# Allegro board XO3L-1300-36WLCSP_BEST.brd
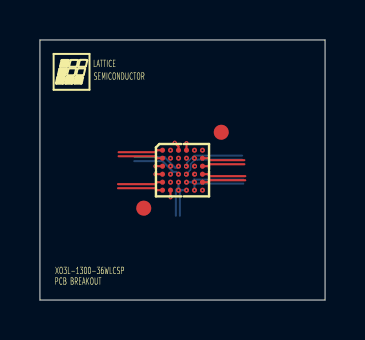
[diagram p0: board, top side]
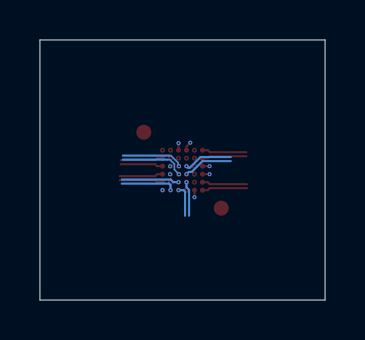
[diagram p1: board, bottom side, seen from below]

Outline 14.28 x 13.02 mm; copper layers: TOP, L2_SIG, L3_PWR, BOTTOM. Coordinates in mm from the lower left corner of the outline.
Outline path: 0,13.02 0,0 14.28,0 14.28,13.02 0,13.02

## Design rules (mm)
net group CDPB6: nets PB6C PB6D
net group CDPB20: nets PB20C PB20D
net group CDPL2: nets PL2C PL2D
net group CDPT10: nets PT10C PT10D
net group CDPT11: nets PT11C PT11D
net group CDPT12: nets PT12C PT12D
net group CDPT15: nets PT15C PT15D
net group CDPT17: nets PT17C PT17D
net group DIFFPAIR0: nets PT10A PT10B
net group DIFFPAIR1: nets PT12A PT12B
net group PB9: nets PB9A PB9B
net group PB11: nets PB11A PB11B
net group PL9: nets PL9A PL9B
net group PT9: nets PT9A PT9B

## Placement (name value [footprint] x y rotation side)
BGA  -  [BGA36N40P6X6_248X254X57B26N]  7.14 6.5 270 top
NOREF  -  []  0.41 10.21 0 top

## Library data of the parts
BGA = BGA36N40P6X6_248X254X57B26N

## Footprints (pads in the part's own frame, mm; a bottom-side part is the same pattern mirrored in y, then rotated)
BGA36N40P6X6_248X254X57B26N
  round 0.75 smd: (-1.9,1.94) (1.9,-1.94)
  round 0.254 smd: A1(-1,-1) A2(-1,-0.6) A3(-1,-0.2) A4(-1,0.2) A5(-1,0.6) A6(-1,1) B1(-0.6,-1) B2(-0.6,-0.6) B3(-0.6,-0.2) B4(-0.6,0.2) B5(-0.6,0.6) B6(-0.6,1) C1(-0.2,-1) C2(-0.2,-0.6) C3(-0.2,-0.2) C4(-0.2,0.2) C5(-0.2,0.6) C6(-0.2,1) D1(0.2,-1) D2(0.2,-0.6) D3(0.2,-0.2) D4(0.2,0.2) D5(0.2,0.6) D6(0.2,1) E1(0.6,-1) E2(0.6,-0.6) E3(0.6,-0.2) E4(0.6,0.2) E5(0.6,0.6) E6(0.6,1) F1(1,-1) F2(1,-0.6) F3(1,-0.2) F4(1,0.2) F5(1,0.6) F6(1,1)

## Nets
GND: BGA.C5 BGA.D1
VCC: BGA.C1 BGA.D5
VCCIO0: BGA.A3
VCCIO2: BGA.F2
VCCIO3: BGA.F6
PB4C: BGA.E5
PB6C: BGA.F5
PB6D: BGA.E4
PB9A: BGA.E3
PB9B: BGA.F4
PB11A: BGA.E2
PB11B: BGA.F3
PB20C: BGA.E1
PB20D: BGA.F1
PL2C: BGA.C6
PL2D: BGA.B6
PL9A: BGA.D6
PL9B: BGA.E6
PT9A: BGA.A6
PT9B: BGA.B5
PT10A: BGA.D4
PT10B: BGA.C4
PT10C: BGA.B4
PT10D: BGA.A5
PT11C: BGA.D3
PT11D: BGA.C3
PT12A: BGA.A4
PT12B: BGA.B3
PT12C: BGA.D2
PT12D: BGA.C2
PT15C: BGA.B2
PT15D: BGA.A2
PT17C: BGA.B1
PT17D: BGA.A1

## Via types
v1: diameter 0.203, hole 0.102, TOP to BOTTOM, 16 vias
v2: diameter 0.203, hole 0.102, TOP to L2_SIG, 12 vias

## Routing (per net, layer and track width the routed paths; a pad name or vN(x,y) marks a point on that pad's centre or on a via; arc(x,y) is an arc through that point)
GND: length 0.4
  TOP w0.102: BGA.D1 v1(5.78,6.3)
  vias: v1(7.76,6.7)
VCC: length 0.4
  TOP w0.102: BGA.D5 7.75,6.3 v1(7.76,6.3) ; BGA.C1 v1(5.78,6.7)
VCCIO0: length 0.5
  TOP w0.102: BGA.A3 6.94,7.69 v1(6.75,7.88)
VCCIO2: length 0.4
  TOP w0.102: BGA.F2 v1(6.54,5.14)
VCCIO3:
  vias: v1(8.14,5.5)
PB4C: length 2.5
  L2_SIG w0.102: v2(7.74,5.9) 10.21,5.9
PB6C: length 2.7
  BOTTOM w0.102: v1(7.74,5.5) 7.74,5.76 7.81,5.83 10.18,5.83
PB6D: length 2.9
  BOTTOM w0.102: v1(7.34,5.9) 7.6,5.9 7.73,6.03 10.18,6.03
PB9A: length 1.7
  BOTTOM w0.102: v1(6.94,5.9) 6.94,5.64 6.81,5.51 6.81,4.22
PB9B: length 1.6
  BOTTOM w0.102: v1(7.34,5.5) 7.08,5.5 7.01,5.43 7.01,4.22
PB11A: length 1.9
  L2_SIG w0.102: 6.02,4.22 6.02,5.27 6.54,5.79 v2(6.54,5.9)
PB11B: length 1.9
  TOP w0.102: BGA.F3 v2(6.94,5.5)
  L2_SIG w0.102: v2(6.94,5.5) 6.85,5.58 6.62,5.58 6.23,5.19 6.23,4.22
PB20C: length 2.3
  TOP w0.102: BGA.E1 5.87,5.9 5.77,5.8 3.91,5.8
PB20D: length 2.3
  TOP w0.102: BGA.F1 5.87,5.5 5.77,5.6 3.91,5.6
PL2C: length 2.1
  TOP w0.102: 10.24,6.8 8.51,6.8 8.41,6.7 BGA.C6
PL2D: length 2.1
  TOP w0.102: 10.24,7 8.51,7 8.41,7.1 BGA.B6
PL9A: length 2.2
  TOP w0.102: BGA.D6 8.41,6.3 8.51,6.2 10.28,6.2
PL9B: length 2.2
  TOP w0.102: BGA.E6 8.41,5.9 8.51,6 10.28,6
PT9A: length 2.4
  L2_SIG w0.102: 10.23,7.17 8.21,7.17 8.14,7.24 8.14,7.5 v2(8.14,7.5)
PT9B: length 2.5
  L2_SIG w0.102: 10.23,6.97 8.13,6.97 8,7.1 7.74,7.1 v2(7.74,7.1)
PT10A: length 3.3
  BOTTOM w0.076: v1(7.31,6.3) 7.54,6.53 7.54,6.81 7.77,7.03 7.88,7.03
  BOTTOM w0.102: 10.13,7.03 7.88,7.03
PT10B: length 3.1
  BOTTOM w0.076: v1(7.31,6.7) 7.35,6.73 7.35,6.87 7.72,7.23 7.81,7.23
  BOTTOM w0.102: 7.81,7.23 10.13,7.23
PT10C: length 1.9
  L2_SIG w0.102: 7.59,8.91 7.59,7.75 7.34,7.5 v2(7.34,7.1)
PT10D: length 1.4
  L2_SIG w0.102: v2(7.74,7.5) 7.74,7.61 7.8,7.67 7.8,8.91
PT11C: length 2.5
  BOTTOM w0.102: 4.72,6.95 6.14,6.95 6.67,6.42 6.82,6.42 v1(6.94,6.3)
PT11D: length 2.5
  BOTTOM w0.102: v1(6.94,6.7) 6.87,6.63 6.77,6.63 6.24,7.16 4.72,7.16
PT12A: length 1.5
  TOP w0.102: BGA.A4 v1(7.34,7.86)
  L2_SIG w0.102: v1(7.34,7.86) 7.22,7.97 7.22,8.91
PT12B: length 1.8
  L2_SIG w0.102: 7.02,8.91 7.02,7.19 v2(6.94,7.1)
PT12C: length 2.2
  L2_SIG w0.102: v2(6.54,6.3) 6.49,6.35 6.39,6.35 6.24,6.2 6.24,6.11 5.97,5.84 4.63,5.84
PT12D: length 2.2
  L2_SIG w0.102: v2(6.54,6.7) 6.54,6.7 6.4,6.55 6.31,6.55 6.04,6.28 6.04,6.19 5.89,6.05 4.63,6.05
PT15C: length 1.9
  L2_SIG w0.102: v2(6.54,7.1) 6.44,7.2 4.71,7.2
PT15D: length 1.9
  L2_SIG w0.102: 4.71,7.4 6.44,7.4 v2(6.54,7.5)
PT17C: length 2.2
  TOP w0.102: 3.94,7.2 5.77,7.2 5.87,7.1 BGA.B1
PT17D: length 2.2
  TOP w0.102: 3.94,7.4 5.77,7.4 5.87,7.5 BGA.A1

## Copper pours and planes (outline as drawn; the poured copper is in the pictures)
GND on L3_PWR: 5.46,5.95 5.46,6.44 6.59,6.44 6.59,7.05 8.15,7.05 8.15,6.53 7.29,6.53 7.29,5.95
VCC on L3_PWR: 7.39,5.95 7.39,6.43 8.25,6.43 8.25,7.15 6.49,7.15 6.49,6.55 5.46,6.55 5.46,7.45 7.13,7.45 7.13,7.8 7.39,7.8 7.39,8.28 8.83,8.28 8.83,5.95
VCCIO0 on L3_PWR: 5.46,7.55 5.46,8.28 7.29,8.28 7.29,7.9 7.03,7.9 7.03,7.55
VCCIO2 on L3_PWR: 5.46,4.67 5.46,5.85 6.89,5.85 6.89,4.67
VCCIO3 on L3_PWR: 6.99,4.67 6.99,5.85 7.39,5.85 8.83,5.85 8.83,4.67

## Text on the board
User.Comments: ASP | CHRIS WEST | 07/01/14 | 07/14/14 | DWG NO: | XO3L-1300-36WLCSP | REVISION | 2.0 | SHEET | 1 | OF | XO3L-1300-36WLCSP PCB BREAKOUT | LATTICE SEMICONDUCTOR CORPORATION
Ref Des/Silkscreen Top: PCB BREAKOUT | XO3L-1300-36WLCSP | LATTICE | SEMICONDUCTOR
L3_PWR: A | B | C | D | E | F | 1 | 2 | 3 | 4 | 5 | 6
PAGE_OUTLINE: SPECIAL INSTRUCTIONS: | USE 1/2 OUNCE COPPER FOR BOTH INTERNAL AND EXTERNAL LAYERS | VIAS ARE TO BE NON-CONDUCTIVE EPOXY FILLED | PLANARIZE AT TOP AND BOTTOM | BOARD THICKNESS IS 62MILS | SIGNAL         (L2) | POWER/GND PLANE (L3) | PRIMARY SIDE   (L1) | SECONDARY SIDE (L4) | SECONDARY SILKSCREEN | SECONDARY SOLDERMASK | PRIMARY SOLDERMASK | PRIMARY SILKSCREEN | DESIGNED BY: | APPROVED BY: | SIGNATURES         DATE | REV | 1 | INITIAL RELEASE | NECK DOWNTRACE WIDTH/SPACE | ESCAPE VIA DRILL | TRACE WIDTH/SPACE | ARRAY SIZE | ESCAPE VIA PAD | BGA LAND OPENING | PACKAGE SIZE | BGA LAND PAD | PITCH | DESCRIPTION | 2.487x2.541 | 0.1016 | 0.0762 | 0.2032 | 0.25 | 6 X 6 | 0.40 | MM | 07/14/2014 | DATE | 10.00 | 15.748 | MILS | 8.00 | 4.00 | 4/4 | 3 | APPROVED | C. WEST | 4 LAYER STACKUP | PCB BREAKOUT DETAILS | REVISION
PLACE_BOUND_TOP: FIGURE | SIZE | 4.0 | DRILL CHART: TOP to BOTTOM | ALL UNITS ARE IN MILS | PLATED | QTY | 16
User.5: FIGURE | SIZE | 4.0 | DRILL CHART: TOP to L2_SIG | ALL UNITS ARE IN MILS | PLATED | QTY | 12
